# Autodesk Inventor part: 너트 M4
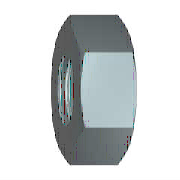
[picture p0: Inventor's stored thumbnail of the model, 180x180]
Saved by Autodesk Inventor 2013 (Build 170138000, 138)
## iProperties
IsCustomPart: 0
Created: 2012-02
Part Number: 너트 M4
Material: 스테인리스강
Description: 6각 너트, 스타일 1 - 제품 등급 A 및 B
Document SubType Name: Modeling
Standard: ISO 4032
Designer: mduedu
Standard Revision: Third edition 1999-08-15
Standards Organization: ISO
Language: ko-KR
Size Designation: M4
Categories: <MemberInstance><Categories><Category DisplayName="조임쇠" InternalName="e4da775c-781d-43d5-af7c-5136215cf5a6" Mnemonic="FSTN"><Category DisplayName="너트" InternalN
Density: 8.08 g/cm^3
Mass: 0.820715 g
Surface Area: 1.59496 cm^2
Volume: 0.101574 cm^3
Author: mduedu
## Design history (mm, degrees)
sketch "스케치1"
  geometry: L1 (-4.041, 0)-(-2.021, 3.5); L2 (-2.021, 3.5)-(2.021, 3.5); L3 (2.021, 3.5)-(4.041, 0); L4 (4.041, 0)-(2.021, -3.5); L5 (2.021, -3.5)-(-2.021, -3.5); L6 (-2.021, -3.5)-(-4.041, 0); 2 further points
  constraints: 12 end point, 1 coincident, 1 horizontal, 11 other
  dimensions: "d0" = 8.0829 distance of L3.end L1.start (= 1.1547 x SW)
extrude "본체" new body sketch "스케치1" distance "d1" = 3.2 (= KOH); taper "d2" = 0 deg
sketch "스케치2"
  geometry: L1 (0, 2.021)-(0, 4.041) reference; L2 (0, 4.041)-(3.2, 4.041) reference; L3 (3.2, 2.021)-(3.2, 4.041) reference; L4 (-0.64, 0)-(3.84, 0) reference; L5 (0.63, 4.041)-(0, 2.95); L6 (2.57, 4.041)-(3.2, 2.95)
  constraints: 4 end point, 4 point on line
  dimensions: "d3" = 30 deg angle of L1 L5 (= ANG1); "d4" = 30 deg angle of L3 L6 (= ANG2); "d5" = 5.9 diameter of L5.end L4 (= SW0); "d6" = 5.9 diameter of L6.end L4 (= SW01)
revolve "모따기1" sketch "스케치2" stored, may be unused: angle "d7" = 90 deg
sketch "스케치3"
  geometry: 4 further points
  constraints: 1 coincident, 1 other
hole "스레드" sketch "스케치3" at (0, 0) diameter "d25" = 3.242; stored, may be unused: countersink angle "d29" = 82 deg, drill point angle "d31" = 118 deg; dims "d26" = 6, "d27" = 4, "d28" = 2, "d30" = 8
workaxis "Work Axis1"
workplane "Work Plane1"
body "Solid1"
chamfer "모따기2" distance "d8" = 0.37889 (= -0.5 x GD1 + 0.5 x NND); stored, may be unused: angle "d9" = 30 deg, second distance "d40" = 0.37889 (= -0.5 x GD1 + 0.5 x NND)
chamfer "모따기3" distance "d10" = 0.37889 (= -0.5 x GD1 + 0.5 x NND); stored, may be unused: angle "d11" = 30 deg, second distance "d41" = 0.37889 (= -0.5 x GD1 + 0.5 x NND)
other parameters: "ANG1" = 30 deg [user parameter; used in 1 equation term], "ANG2" = 30 deg [user parameter; used in 1 equation term], "NND" = 4 [user parameter; used in 4 equation terms], "KOH" = 3.2 [user parameter; used in 1 equation term], "SW" = 7 [user parameter; used in 2 equation terms], "SW0" = 5.9 [user parameter; used in 2 equation terms], "SW01" = 5.9 (= SW0) [user parameter; used in 1 equation term], "GD1" = 3.24223 (computed from THREADDIA, PTC, TOA) [user parameter; used in 4 equation terms], "d13" = 0, "d14" = 0, "d39" = 0, "d42" = 0, "GUL" = 0.37889 (= 0.541266 x PTC) [user parameter], "TPU" = 14.28571 (computed from PTC) [user parameter], "THREADDIA" = 4 [user parameter; used in 1 equation term], "TOA" = 30 deg [user parameter; used in 1 equation term], "PTC" = 0.7 [user parameter; used in 4 equation terms], "E0" = 8.085 (= 1.155 x SW) [user parameter], "GAL" = 0.37889 (= 0.541266 x PTC) [user parameter]
